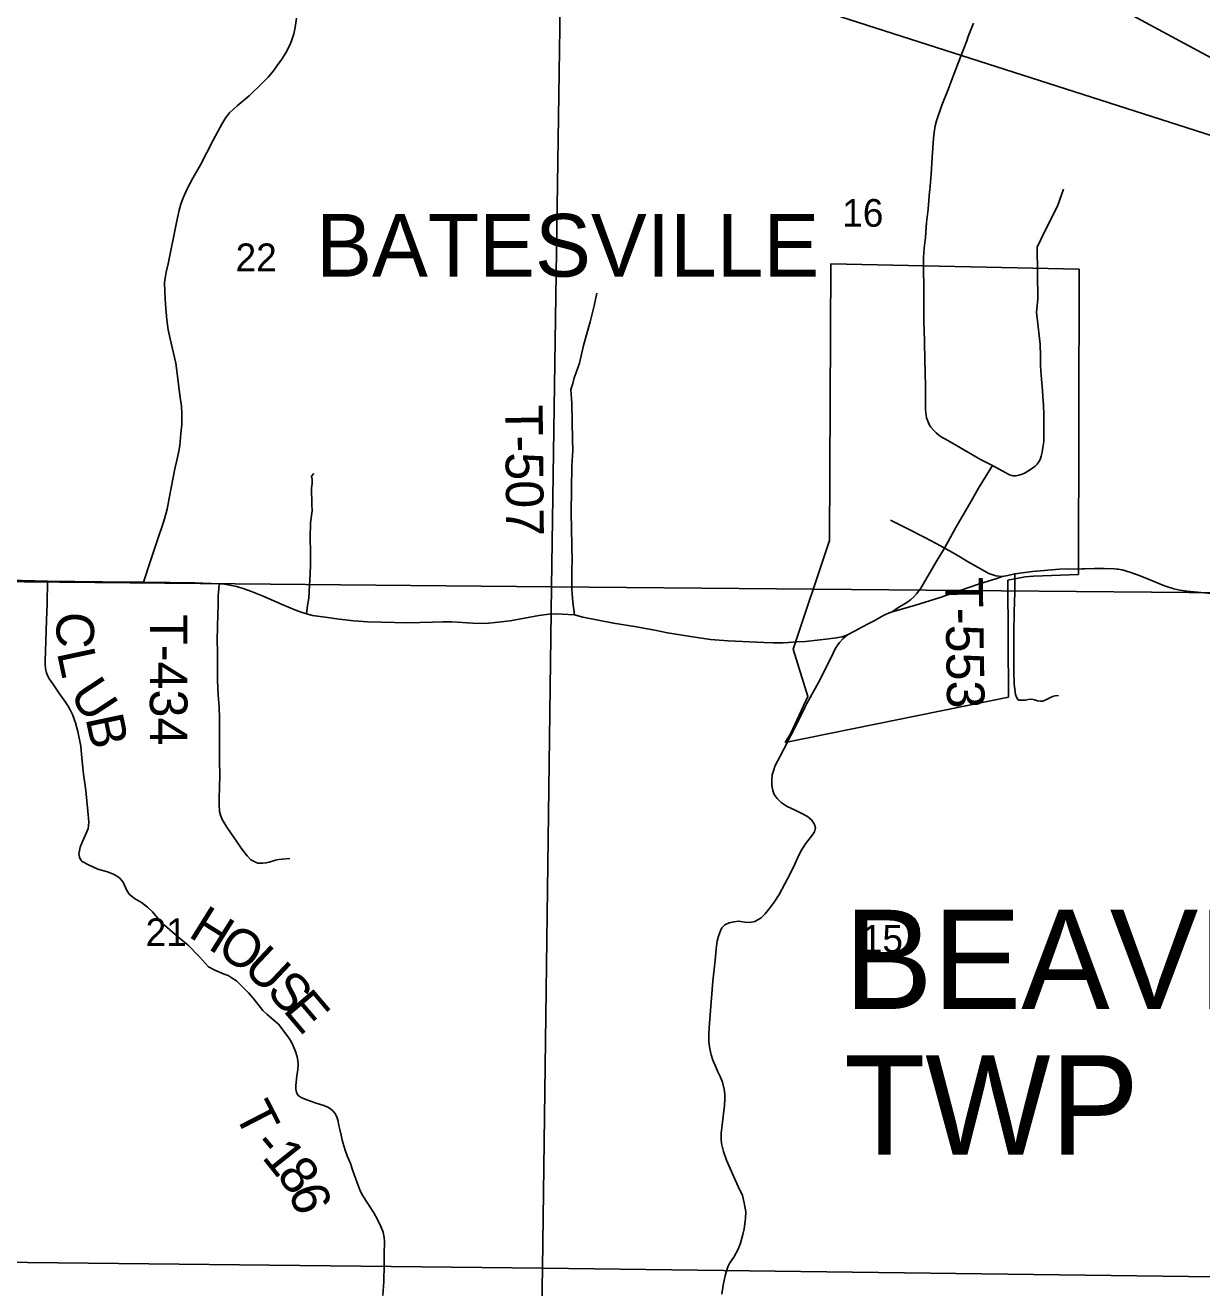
# Model space of a CAD drawing. Extents: x 0 to 34, y 0 to 22.
# Drawn here: x 3.307 to 5.085, y 15.399 to 17.307 of the extents above; entities that cross this region are included whole.
import ezdxf

# ---------------------------------------------------------------- set-up
doc = ezdxf.new("R2010")
doc.units = 0
for name, color, linetype in [('GM_X_City_Street', 7, 'Continuous'), ('GM_X_Corporation', 7, 'Continuous'), ('GM_X_Corporation_Text', 7, 'Continuous'), ('GM_X_County_Road', 7, 'Continuous'), ('GM_X_Section_Text', 7, 'Continuous'), ('GM_X_State_Route', 7, 'Continuous'), ('GM_X_Township_Road', 7, 'Continuous'), ('GM_X_Township_Road_Text', 7, 'Continuous'), ('GM_X_Township_Text', 7, 'Continuous'), ('SH_Text', 7, 'Continuous')]:
    doc.layers.add(name, color=color, linetype=linetype)

msp = doc.modelspace()

# ---------------------------------------------------------------- linework, layer by layer
at = {"layer": 'GM_X_City_Street'}
for points in [[(4.6146, 16.5592), (4.64, 16.5467), (4.6674, 16.5328), (4.69, 16.5208), (4.696, 16.5173), (4.7046, 16.5124)], [(4.7046, 16.5124), (4.7201, 16.5036), (4.731, 16.4967), (4.7629, 16.4786), (4.7736, 16.4753), (4.7835, 16.4741)]]:
    msp.add_lwpolyline(points, dxfattribs=at)
at = {"layer": 'GM_X_Corporation'}
for points in [[(3.1011, 17.4796), (4.1176, 17.4733), (4.1025, 16.4586), (3.0928, 16.4681)], [(4.1176, 17.4733), (5.1353, 17.4571), (5.122, 16.4496), (4.1025, 16.4586)], [(4.1025, 16.4586), (4.0887, 15.4288), (3.0813, 15.4398), (3.0928, 16.4681)], [(5.122, 16.4496), (5.1041, 15.416), (4.0887, 15.4288), (4.1025, 16.4586)], [(3.0813, 15.4398), (4.0887, 15.4288), (4.0718, 14.4088), (3.0687, 14.4122)], [(4.0887, 15.4288), (5.1041, 15.416), (5.088, 14.3982), (4.0718, 14.4088)]]:
    msp.add_lwpolyline(points, close=True, dxfattribs=at)
at = {"layer": 'GM_X_County_Road'}
msp.add_lwpolyline([(3.7171, 17.3181), (3.715, 17.3038), (3.7128, 17.2942), (3.7097, 17.284), (3.7058, 17.2752), (3.7009, 17.2656), (3.6947, 17.2562), (3.6881, 17.2464), (3.6821, 17.2387), (3.6745, 17.229), (3.6654, 17.2197), (3.6455, 17.2008), (3.6274, 17.1857), (3.6159, 17.1748), (3.6103, 17.168), (3.6041, 17.1578), (3.591, 17.1335), (3.5719, 17.0966), (3.5606, 17.0765), (3.5523, 17.0613), (3.5456, 17.0465), (3.5423, 17.0368), (3.5397, 17.0278), (3.5355, 17.0095), (3.523, 16.9467), (3.5203, 16.9342), (3.5184, 16.9251), (3.5177, 16.9183), (3.5183, 16.9051), (3.5187, 16.895), (3.519, 16.8855), (3.521, 16.8623), (3.523, 16.847), (3.526, 16.8337), (3.5292, 16.8202), (3.5348, 16.7969), (3.5413, 16.7449), (3.5431, 16.7316), (3.5437, 16.7203), (3.5436, 16.704), (3.5424, 16.6905), (3.5408, 16.6724), (3.539, 16.6612), (3.5329, 16.6345), (3.5253, 16.5953), (3.5215, 16.576), (3.5176, 16.5612), (3.5146, 16.5517), (3.5074, 16.5313), (3.4958, 16.4963), (3.4857, 16.4657)], dxfattribs=at)
at = {"layer": 'GM_X_State_Route'}
for points in [[(4.6737, 17.0558), (4.6738, 17.0579), (4.6762, 17.0824), (4.6774, 17.1077), (4.6796, 17.1369), (4.6805, 17.1451), (4.6821, 17.1553), (4.6839, 17.1627), (4.6919, 17.1866), (4.7015, 17.2105), (4.7107, 17.2346), (4.7232, 17.267), (4.7298, 17.2839), (4.7319, 17.2902), (4.7401, 17.3107)], [(4.6642, 16.9562), (4.6656, 16.9707), (4.6674, 16.9864), (4.669, 17.0093), (4.6716, 17.0295), (4.6737, 17.0558)], [(4.6172, 16.421), (4.6254, 16.4268), (4.639, 16.4351), (4.6447, 16.4389), (4.6498, 16.4435), (4.654, 16.448), (4.6576, 16.4528), (4.6603, 16.4566), (4.6837, 16.4964), (4.696, 16.5173), (4.7134, 16.5484), (4.7364, 16.5882), (4.7475, 16.6078), (4.7685, 16.6418), (4.7507, 16.6513), (4.7141, 16.6721), (4.6976, 16.6816), (4.6926, 16.6844), (4.6878, 16.6878), (4.6834, 16.6914), (4.6793, 16.6955), (4.6757, 16.6998), (4.6731, 16.7038), (4.6708, 16.7091), (4.6692, 16.7139), (4.6676, 16.7264), (4.6672, 16.7465), (4.6673, 16.7612), (4.6665, 16.8033), (4.666, 16.8272), (4.6653, 16.8486), (4.6651, 16.8567), (4.6651, 16.8828), (4.6649, 16.9107), (4.6644, 16.9393), (4.6642, 16.9562)], [(4.6172, 16.421), (4.6506, 16.4306), (4.6894, 16.4425), (4.7429, 16.4614), (4.7541, 16.4648), (4.7635, 16.4678), (4.7737, 16.4708), (4.7835, 16.4741), (4.7918, 16.4759), (4.8024, 16.4782), (4.8292, 16.4819), (4.8698, 16.4855), (4.9036, 16.4857), (4.9084, 16.4858)], [(4.9084, 16.4858), (4.9229, 16.4862), (4.9376, 16.4863), (4.9523, 16.486), (4.9567, 16.4855)], [(3.2617, 16.469), (3.3407, 16.467), (3.4232, 16.4661), (3.4857, 16.4657), (3.5258, 16.4654), (3.5632, 16.4648), (3.6004, 16.4634), (3.6083, 16.4625), (3.6161, 16.4614), (3.6262, 16.4593), (3.6367, 16.4562), (3.6493, 16.4516), (3.6667, 16.4446), (3.6955, 16.432), (3.7143, 16.4241), (3.7239, 16.4203), (3.7321, 16.4176), (3.7414, 16.4154), (3.7602, 16.4129), (3.7816, 16.41), (3.8038, 16.4072), (3.8247, 16.4058), (3.8851, 16.404), (3.9228, 16.4053), (3.9382, 16.406), (3.952, 16.4058), (3.9837, 16.4035), (4.003, 16.4033), (4.022, 16.4051), (4.0398, 16.4075), (4.0831, 16.4153), (4.0989, 16.4174), (4.1093, 16.4179), (4.1183, 16.4175), (4.137, 16.4161), (4.1496, 16.4129), (4.196, 16.4037), (4.2277, 16.3989), (4.2585, 16.3931), (4.2776, 16.3893), (4.3, 16.3854), (4.319, 16.3828), (4.3426, 16.3791), (4.3692, 16.3771), (4.4233, 16.3747), (4.4378, 16.3739), (4.4525, 16.3741), (4.4603, 16.3744), (4.4732, 16.3753)], [(4.9567, 16.4855), (4.9584, 16.4854), (4.9645, 16.4843), (4.9763, 16.4809), (4.9917, 16.4754), (5.0056, 16.4696), (5.0287, 16.4603), (5.0427, 16.4554), (5.0519, 16.4535), (5.0621, 16.452), (5.0996, 16.4488)], [(4.5498, 16.3862), (4.56, 16.3916), (4.5712, 16.3975), (4.5809, 16.4027), (4.5888, 16.4069), (4.6031, 16.4148), (4.6092, 16.4179), (4.6172, 16.421)], [(4.4732, 16.3753), (4.486, 16.3762), (4.5215, 16.3801)], [(4.4853, 16.2761), (4.4883, 16.2823), (4.5057, 16.3143), (4.5242, 16.3506), (4.5317, 16.3658), (4.5375, 16.3747), (4.5429, 16.3805), (4.5498, 16.3862)], [(4.5215, 16.3801), (4.5326, 16.3814), (4.5413, 16.383), (4.5498, 16.3862)], [(4.4537, 16.2144), (4.4639, 16.2341), (4.4796, 16.2645), (4.4853, 16.2761)], [(4.3597, 15.3897), (4.3618, 15.4031), (4.3647, 15.4175), (4.3667, 15.4245), (4.3688, 15.4309), (4.3718, 15.4368), (4.3781, 15.4458), (4.3845, 15.4574), (4.3877, 15.4668), (4.3915, 15.4797), (4.3933, 15.4885), (4.3947, 15.4961), (4.3956, 15.5047), (4.3958, 15.514), (4.3935, 15.5276), (4.3908, 15.5387), (4.3845, 15.5526), (4.3781, 15.5669), (4.367, 15.5923), (4.362, 15.6051), (4.3593, 15.6175), (4.3588, 15.6244), (4.3588, 15.6328), (4.3602, 15.6452), (4.3624, 15.6629), (4.364, 15.6745), (4.3643, 15.6847), (4.3642, 15.6918), (4.3631, 15.6997), (4.3606, 15.71), (4.3572, 15.7184), (4.3538, 15.7259), (4.35, 15.7343), (4.3461, 15.7431), (4.3436, 15.7513), (4.3415, 15.7602), (4.3402, 15.771), (4.34, 15.7836), (4.3411, 15.799), (4.3434, 15.8308), (4.3463, 15.8628), (4.3497, 15.8944), (4.3508, 15.9057), (4.3513, 15.9123), (4.3527, 15.9232), (4.3545, 15.9309), (4.3577, 15.9389), (4.3599, 15.9431), (4.3643, 15.9477), (4.3709, 15.9509), (4.3779, 15.9525), (4.3856, 15.9532), (4.3947, 15.952), (4.402, 15.9514), (4.4097, 15.953), (4.419, 15.9582), (4.4251, 15.9643), (4.4312, 15.9718), (4.4388, 15.9823), (4.4462, 15.9938), (4.4547, 16.0099), (4.4633, 16.0261), (4.4699, 16.0395), (4.4739, 16.0486), (4.4789, 16.0592), (4.4862, 16.0702), (4.4967, 16.084), (4.4996, 16.0883), (4.501, 16.0942), (4.4996, 16.0995), (4.4958, 16.106), (4.4892, 16.1115), (4.4808, 16.1163), (4.4706, 16.121), (4.4583, 16.1269), (4.4494, 16.1328), (4.4431, 16.1388), (4.4388, 16.1446), (4.4367, 16.151), (4.4354, 16.1583), (4.4353, 16.1665), (4.436, 16.1744), (4.4378, 16.1807), (4.4405, 16.1885), (4.4478, 16.2028), (4.4537, 16.2144)]]:
    msp.add_lwpolyline(points, dxfattribs=at)
at = {"layer": 'GM_X_Township_Road'}
for points in [[(4.7685, 16.6418), (4.7787, 16.6366), (4.7942, 16.6277), (4.7999, 16.6265), (4.8044, 16.6262), (4.8084, 16.6272), (4.8137, 16.6288), (4.8178, 16.6307), (4.8223, 16.6335), (4.8276, 16.637), (4.8331, 16.6411), (4.8363, 16.6442), (4.8395, 16.6489), (4.8412, 16.6527), (4.842, 16.6562), (4.8435, 16.6621), (4.8448, 16.6693), (4.846, 16.6784), (4.8464, 16.6897), (4.8461, 16.7055), (4.8461, 16.7188), (4.8455, 16.7339), (4.8449, 16.7462), (4.8444, 16.7552), (4.8423, 16.7784), (4.8412, 16.7925), (4.841, 16.8076), (4.8405, 16.8253), (4.835, 16.8737), (4.8374, 16.8935), (4.8362, 16.972), (4.8476, 16.9963), (4.8668, 17.0338), (4.8758, 17.0596)], [(4.171, 16.9023), (4.167, 16.8834), (4.1607, 16.8591), (4.1509, 16.8235), (4.1449, 16.7966), (4.1395, 16.7826), (4.1368, 16.7743), (4.1344, 16.766), (4.1317, 16.7569), (4.133, 16.7359), (4.134, 16.6812), (4.1347, 16.6651), (4.1333, 16.6408), (4.1322, 16.5712), (4.1334, 16.4962), (4.1333, 16.4875), (4.1329, 16.466), (4.1331, 16.4558), (4.1337, 16.4484), (4.1347, 16.4355), (4.1354, 16.428), (4.137, 16.4161)], [(3.7321, 16.4176), (3.7338, 16.4303), (3.7355, 16.4417), (3.7368, 16.4612), (3.7375, 16.4776), (3.7382, 16.4926), (3.738, 16.5119), (3.7375, 16.5322), (3.738, 16.5555), (3.7407, 16.5733), (3.7404, 16.5834), (3.7396, 16.6076), (3.7409, 16.6146), (3.7407, 16.6207), (3.7395, 16.6258), (3.7432, 16.6299)], [(3.8475, 15.3878), (3.8488, 15.4087), (3.8497, 15.4338), (3.8495, 15.4561), (3.8498, 15.4633), (3.8498, 15.4691), (3.8494, 15.4754), (3.8481, 15.4831), (3.8446, 15.4919), (3.8393, 15.5026), (3.8337, 15.5123), (3.8237, 15.5284), (3.8171, 15.5383), (3.8134, 15.5458), (3.8112, 15.5511), (3.8081, 15.5596), (3.8044, 15.5706), (3.8019, 15.5777), (3.7985, 15.5871), (3.7936, 15.5987), (3.7905, 15.6075), (3.7863, 15.6223), (3.7844, 15.6301), (3.7827, 15.6383), (3.7812, 15.6445), (3.7801, 15.6505), (3.7784, 15.6559), (3.7769, 15.6599), (3.7749, 15.6633), (3.772, 15.6667), (3.7684, 15.6698), (3.7645, 15.6724), (3.7582, 15.6748), (3.7466, 15.6783), (3.7381, 15.6811), (3.73, 15.6843), (3.7239, 15.687), (3.7197, 15.6899), (3.7169, 15.6946), (3.7162, 15.6993), (3.716, 15.7051), (3.7178, 15.7195), (3.7193, 15.729), (3.7197, 15.7362), (3.7193, 15.7429), (3.7181, 15.7483), (3.7156, 15.7562), (3.7121, 15.7649), (3.7088, 15.7717), (3.7039, 15.779), (3.69, 15.7975), (3.6729, 15.8122), (3.6661, 15.8185), (3.6515, 15.8372), (3.6444, 15.8452), (3.6352, 15.8547), (3.6262, 15.8631), (3.6198, 15.8674), (3.6136, 15.8711), (3.6079, 15.8732), (3.5936, 15.8791), (3.5842, 15.8841), (3.5706, 15.8994), (3.5527, 15.9178), (3.5404, 15.9279), (3.5174, 15.9474), (3.5091, 15.956), (3.4995, 15.9674), (3.4921, 15.9744), (3.4831, 15.9815), (3.4721, 15.9874), (3.4643, 15.9942), (3.4601, 16.0006), (3.4551, 16.0121), (3.4498, 16.0186), (3.4418, 16.0238), (3.4313, 16.0278), (3.4167, 16.0321), (3.4028, 16.0386), (3.3934, 16.0433), (3.3908, 16.0465), (3.3892, 16.0503), (3.3884, 16.0551), (3.389, 16.0599), (3.3902, 16.0651), (3.3935, 16.0738), (3.3999, 16.0872), (3.4021, 16.0933), (3.4028, 16.0976), (3.4032, 16.1033), (3.4018, 16.1196), (3.3988, 16.1509), (3.3953, 16.1757), (3.3921, 16.2055), (3.3911, 16.218), (3.3866, 16.2401), (3.3832, 16.2529), (3.3786, 16.2657), (3.3753, 16.2728), (3.3721, 16.2784), (3.3682, 16.2844), (3.3579, 16.2986), (3.3488, 16.3118), (3.344, 16.319), (3.341, 16.3245), (3.3388, 16.33), (3.3377, 16.3352), (3.3371, 16.3416), (3.3373, 16.3461), (3.3384, 16.377), (3.3393, 16.4082), (3.3401, 16.4328), (3.3407, 16.467)], [(4.8024, 16.4782), (4.8022, 16.4683), (4.8025, 16.4513), (4.8014, 16.4203), (4.8007, 16.3892), (4.8007, 16.3607), (4.8011, 16.3314), (4.8016, 16.3119), (4.8025, 16.3034), (4.8036, 16.2958), (4.805, 16.292), (4.8071, 16.2884), (4.8089, 16.2876), (4.8126, 16.2872), (4.8183, 16.2876), (4.8227, 16.2882), (4.8281, 16.2887), (4.832, 16.2881), (4.8365, 16.2866), (4.8412, 16.2859), (4.8444, 16.2859), (4.8474, 16.2868), (4.8535, 16.29), (4.8593, 16.293), (4.8632, 16.2939), (4.8684, 16.2946)], [(3.6004, 16.4634), (3.5995, 16.4552), (3.5987, 16.4453), (3.5986, 16.4318), (3.5978, 16.3998), (3.5974, 16.3763), (3.5976, 16.362), (3.5975, 16.3454), (3.5979, 16.3178), (3.5987, 16.2949), (3.6, 16.2766), (3.6008, 16.2608), (3.6008, 16.2373), (3.6005, 16.1958), (3.601, 16.1736), (3.6005, 16.1557), (3.6001, 16.1387), (3.6002, 16.1295), (3.6008, 16.1193), (3.602, 16.1135), (3.6048, 16.1068), (3.6086, 16.1005), (3.6118, 16.0955), (3.6184, 16.0861), (3.6253, 16.0759), (3.6335, 16.0638), (3.6426, 16.0521), (3.6483, 16.0463), (3.6529, 16.0433), (3.6559, 16.0421), (3.6585, 16.0412), (3.6613, 16.0409), (3.6661, 16.0408), (3.6708, 16.0414), (3.6759, 16.0426), (3.6853, 16.0453), (3.6902, 16.0465), (3.6955, 16.0472), (3.7071, 16.0482)]]:
    msp.add_lwpolyline(points, dxfattribs=at)
at = {"layer": 'GM_X_Township_Text'}
msp.add_lwpolyline([(4.4556, 16.2233), (4.464, 16.2377), (4.4896, 16.2927), (4.4673, 16.3644), (4.5226, 16.5286), (4.5244, 16.9466), (4.8994, 16.9386), (4.8986, 16.4774), (4.8307, 16.475), (4.8181, 16.4737), (4.792, 16.4687), (4.7928, 16.2917)], close=True, dxfattribs=at)
at = {"layer": 'SH_Text'}
msp.add_lwpolyline([(5.6379, 16.9679), (4.5397, 17.56), (4.5397, 17.32)], close=True, dxfattribs=at)

# ---------------------------------------------------------------- texts
at = {"layer": 'GM_X_Corporation_Text'}
msp.add_text('BATESVILLE', height=0.0947, rotation=0, dxfattribs=at).set_placement((3.7467, 16.9275))
at = {"layer": 'GM_X_Section_Text'}
for s, p in [('16', (4.5416, 17.0029)), ('22', (3.625, 16.9357)), ('21', (3.4891, 15.9157)), ('15', (4.5712, 15.9059))]:
    msp.add_text(s, height=0.04186, rotation=0, dxfattribs=at).set_placement(p)
at = {"layer": 'GM_X_Township_Road_Text'}
for s, height, rotation, p in [('T-507', 0.05682, 270.5407, (4.0322, 16.7335)), ('T-553', 0.05682, 270.8421, (4.6972, 16.473)), ('C', 0.0568, 267.474, (3.3557, 16.4218)), ('T-434', 0.05682, 270.0032, (3.4955, 16.4175)), ('L', 0.0568, 282.0978, (3.3549, 16.3594)), ('U', 0.0568, 303.4081, (3.3727, 16.2967)), ('B', 0.0568, 281.9315, (3.3981, 16.2602)), ('H', 0.0568, 328.046, (3.5518, 15.931)), ('O', 0.0568, 327.8073, (3.5942, 15.9045)), ('U', 0.0568, 316.7209, (3.6342, 15.8797)), ('S', 0.0568, 312.6576, (3.6699, 15.8462)), ('E', 0.0568, 310.334, (3.6954, 15.8184)), ('T', 0.0568, 297.2129, (3.6221, 15.663)), ('-', 0.0568, 309.7486, (3.649, 15.6139)), ('1', 0.0568, 308.5281, (3.6637, 15.5962)), ('8', 0.0568, 308.5786, (3.6855, 15.5688)), ('6', 0.0568, 287.78, (3.7048, 15.5462))]:
    msp.add_text(s, height=height, rotation=rotation, dxfattribs=at).set_placement(p)
at = {"layer": 'GM_X_Township_Text'}
for s, p in [('BEAVER', (4.5445, 15.8207)), ('TWP', (4.5445, 15.6007))]:
    msp.add_text(s, height=0.15, rotation=0, dxfattribs=at).set_placement(p)

doc.saveas('drawing.dxf')
